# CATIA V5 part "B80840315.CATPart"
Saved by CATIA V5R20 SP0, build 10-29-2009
Part number: B80840315
Revision: 3
Definition: design
Nomenclature: B80840315
Source: made
Description: NOT SPECIFIED
Bounding box of the stored display mesh (mm): x -22.5 to 22.5, y -22.5 to 22.5, z 0 to 315
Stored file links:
  C:\Users\Raffaele\Desktop\3D X SITO CF\BOLEX\4-PILLAR REF 808\B80840315.CATPart
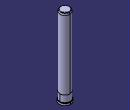
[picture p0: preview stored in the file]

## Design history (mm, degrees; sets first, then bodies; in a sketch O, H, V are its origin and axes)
Body1 "MANIFOLD_SOLID_BREP #450" (main body)
  Solid1: solid without history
